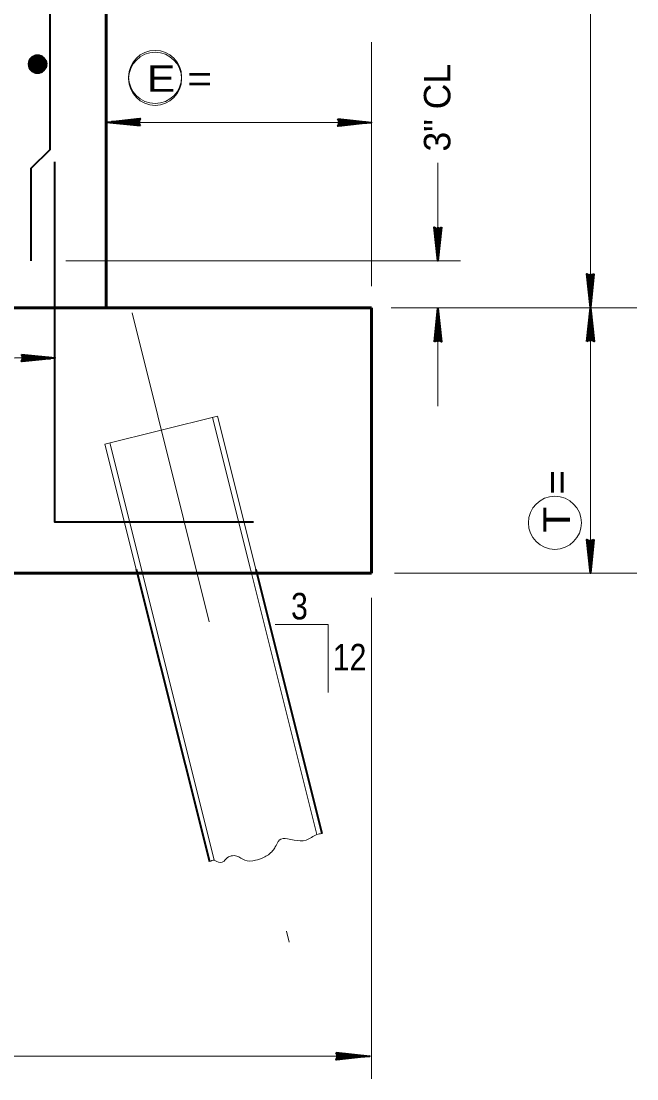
# Model space of a CAD drawing. Extents: x 3.64 to 6.84, y -0.8 to 1.19.
# Drawn here: x 5.2422 to 5.4356, y -0.3007 to 0.0313 of the extents above; entities that cross this region are included whole.
import ezdxf
from ezdxf.enums import TextEntityAlignment as Align

# ---------------------------------------------------------------- set-up
doc = ezdxf.new("R2010")
doc.units = 0
doc.header["$LTSCALE"] = 0.0033
doc.linetypes.add('DOT_DASHED', pattern=[7.7, 5, -1.2, 0.3, -1.2])
doc.linetypes.add('MEDIUM_DASHED', pattern=[4.5, 3, -1.5])
doc.layers.add('1', color=7, linetype='Continuous', lineweight=40)
doc.layers.add('5', color=7, linetype='MEDIUM_DASHED', lineweight=13)

msp = doc.modelspace()

# ---------------------------------------------------------------- linework, layer by layer
at = {"layer": '1', "lineweight": 13}
for p, q in [((5.421, -0.141167), (5.421, 0.274583)), ((5.35225, -0.051917), (5.35225, 0.024667)), ((5.2705, -0.0005), (5.35225, -0.0005)), ((5.373083, -0.034083), (5.373083, -0.01325)), ((5.256167, -0.044), (5.380167, -0.044)), ((5.358417, -0.058667), (5.435583, -0.058667)), ((5.373083, -0.089583), (5.373083, -0.06875)), ((5.304833, -0.142), (5.346833, -0.142)), ((5.359417, -0.142), (5.435583, -0.142)), ((5.35225, -0.149667), (5.35225, -0.300667)), ((5.321917, -0.158083), (5.338583, -0.158083)), ((5.338583, -0.158083), (5.338583, -0.179417)), ((5.018417, -0.2935), (5.35175, -0.2935))]:
    msp.add_line(p, q, dxfattribs=at)
at = {"layer": '1'}
for p, q in [((5.249667, 0.019), (5.248417, 0.020167)), ((5.245167, 0.017083), (5.249083, 0.016333)), ((5.245167, 0.016917), (5.249, 0.016167)), ((5.245167, 0.016667), (5.249, 0.016)), ((5.24525, 0.019333), (5.249833, 0.017167)), ((5.24525, 0.0175), (5.249167, 0.01675)), ((5.245333, 0.017917), (5.249167, 0.017167)), ((5.245333, 0.01775), (5.249167, 0.017)), ((5.245417, 0.018333), (5.24925, 0.017667)), ((5.245417, 0.018167), (5.24925, 0.017417)), ((5.2455, 0.018917), (5.249417, 0.018167)), ((5.2455, 0.01875), (5.249417, 0.018)), ((5.2455, 0.0185), (5.249333, 0.01775)), ((5.245583, 0.019333), (5.2495, 0.018667)), ((5.245583, 0.019167), (5.2495, 0.018417)), ((5.245667, 0.019667), (5.2495, 0.019)), ((5.247583, 0.018833), (5.248917, 0.019833)), ((5.245083, 0.016583), (5.248917, 0.015833)), ((5.245083, 0.016417), (5.248917, 0.015667)), ((5.249417, 0.016167), (5.245667, 0.01575))]:
    msp.add_line(p, q, dxfattribs=at)
at = {"layer": '1', "lineweight": 60}
for p, q in [((5.249833, 0.017167), (5.245083, 0.016417)), ((5.2455, 0.019333), (5.245333, 0.016417)), ((5.24575, 0.019333), (5.2455, 0.016417)), ((5.245917, 0.019333), (5.24575, 0.016333)), ((5.246083, 0.019333), (5.245833, 0.016333)), ((5.24625, 0.019333), (5.246083, 0.016333)), ((5.2465, 0.019333), (5.246333, 0.016333)), ((5.24675, 0.019333), (5.2465, 0.016333)), ((5.246833, 0.01925), (5.246667, 0.016333)), ((5.247, 0.01925), (5.246833, 0.016333)), ((5.247167, 0.01925), (5.247, 0.016333)), ((5.247417, 0.01925), (5.247167, 0.016333)), ((5.247583, 0.01925), (5.247417, 0.016333)), ((5.247833, 0.019167), (5.247583, 0.01625)), ((5.248083, 0.019167), (5.247833, 0.01625)), ((5.24825, 0.019167), (5.248083, 0.01625)), ((5.248333, 0.019167), (5.248167, 0.01625)), ((5.2485, 0.019167), (5.248333, 0.01625)), ((5.248583, 0.019167), (5.248417, 0.01625)), ((5.248833, 0.019083), (5.248583, 0.016167)), ((5.249, 0.019083), (5.248833, 0.016167)), ((5.249167, 0.019083), (5.248917, 0.016167)), ((5.249333, 0.019083), (5.249167, 0.016167)), ((5.249583, 0.019083), (5.249417, 0.016167)), ((5.249833, 0.017167), (5.249667, 0.019)), ((5.35225, -0.058667), (5.35225, -0.142)), ((5.35225, -0.142), (5.018917, -0.142))]:
    msp.add_line(p, q, dxfattribs=at)
at = {"layer": '1', "lineweight": 35}
for p, q in [((5.279333, 0.000583), (5.272, -0.00025)), ((5.279333, 0.000417), (5.272, -0.000333)), ((5.279333, 0.000333), (5.272, -0.0005)), ((5.279417, 0.000167), (5.272083, -0.000583)), ((5.341917, 0.0005), (5.34975, -0.000417)), ((5.341917, 0.0005), (5.34975, -0.000417)), ((5.341917, 0.000417), (5.34975, -0.000417)), ((5.341917, 0.000333), (5.34975, -0.0005)), ((5.341917, 0.000333), (5.34975, -0.000667)), ((5.279583, -0.0005), (5.269, -0.0005)), ((5.279333, -0.001333), (5.2715, -0.000333)), ((5.279333, -0.001333), (5.2715, -0.0005)), ((5.279333, -0.0015), (5.2715, -0.000583)), ((5.279333, -0.0015), (5.2715, -0.000583)), ((5.279333, -0.001417), (5.2715, -0.000583)), ((5.341667, -0.0005), (5.35225, -0.0005)), ((5.341833, -0.001167), (5.349167, -0.000417)), ((5.341917, -0.001333), (5.34925, -0.0005)), ((5.341917, -0.001417), (5.34925, -0.000667)), ((5.341917, -0.001583), (5.34925, -0.00075)), ((5.372, -0.033667), (5.372833, -0.041)), ((5.372167, -0.033667), (5.372917, -0.041)), ((5.37225, -0.033667), (5.373083, -0.041)), ((5.372417, -0.033583), (5.373167, -0.040917)), ((5.373917, -0.033667), (5.372917, -0.0415)), ((5.373083, -0.033417), (5.373083, -0.044)), ((5.373917, -0.033667), (5.373083, -0.0415)), ((5.374083, -0.033667), (5.373167, -0.0415)), ((5.374083, -0.033667), (5.373167, -0.0415)), ((5.374, -0.033667), (5.373167, -0.0415)), ((5.419917, -0.04825), (5.42075, -0.055583)), ((5.420083, -0.04825), (5.420833, -0.055583)), ((5.420167, -0.04825), (5.421, -0.055583)), ((5.420333, -0.048167), (5.421083, -0.0555)), ((5.421833, -0.04825), (5.420833, -0.056083)), ((5.421, -0.048), (5.421, -0.058583)), ((5.421833, -0.04825), (5.421, -0.056083)), ((5.422, -0.04825), (5.421083, -0.056083)), ((5.422, -0.04825), (5.421083, -0.056083)), ((5.421917, -0.04825), (5.421083, -0.056083)), ((5.373083, -0.069417), (5.373083, -0.058833)), ((5.421, -0.06925), (5.421, -0.058667)), ((5.372083, -0.069167), (5.373, -0.061333)), ((5.372083, -0.069167), (5.373, -0.061333)), ((5.372167, -0.069167), (5.373, -0.061333)), ((5.37225, -0.069167), (5.373083, -0.061333)), ((5.37225, -0.069167), (5.37325, -0.061333)), ((5.37375, -0.06925), (5.373, -0.061917)), ((5.373917, -0.069167), (5.373083, -0.061833)), ((5.374, -0.069167), (5.37325, -0.061833)), ((5.374167, -0.069167), (5.373333, -0.061833)), ((5.42, -0.069), (5.420917, -0.061167)), ((5.42, -0.069), (5.420917, -0.061167)), ((5.420083, -0.069), (5.420917, -0.061167)), ((5.420167, -0.069), (5.421, -0.061167)), ((5.420167, -0.069), (5.421167, -0.061167)), ((5.421667, -0.069083), (5.420917, -0.06175)), ((5.421833, -0.069), (5.421, -0.061667)), ((5.421917, -0.069), (5.421167, -0.061667)), ((5.422083, -0.069), (5.42125, -0.061667)), ((5.24225, -0.074417), (5.252833, -0.074417)), ((5.242417, -0.075083), (5.24975, -0.074333)), ((5.2425, -0.073417), (5.250333, -0.074333)), ((5.2425, -0.073417), (5.250333, -0.074333)), ((5.2425, -0.0735), (5.250333, -0.074333)), ((5.2425, -0.073583), (5.250333, -0.074417)), ((5.2425, -0.073583), (5.250333, -0.074583)), ((5.2425, -0.07525), (5.249833, -0.074417)), ((5.2425, -0.075333), (5.249833, -0.074583)), ((5.2425, -0.0755), (5.249833, -0.074667)), ((5.419917, -0.131667), (5.42075, -0.139)), ((5.420083, -0.131667), (5.420833, -0.139)), ((5.420167, -0.131667), (5.421, -0.139)), ((5.420333, -0.131583), (5.421083, -0.138917)), ((5.421833, -0.131667), (5.420833, -0.1395)), ((5.421, -0.131417), (5.421, -0.142)), ((5.421833, -0.131667), (5.421, -0.1395)), ((5.422, -0.131667), (5.421083, -0.1395)), ((5.422, -0.131667), (5.421083, -0.1395)), ((5.421917, -0.131667), (5.421083, -0.1395)), ((5.341083, -0.2935), (5.351667, -0.2935)), ((5.34125, -0.294167), (5.348583, -0.293417)), ((5.341333, -0.2925), (5.349167, -0.293417)), ((5.341333, -0.2925), (5.349167, -0.293417)), ((5.341333, -0.292583), (5.349167, -0.293417)), ((5.341333, -0.292667), (5.349167, -0.2935)), ((5.341333, -0.292667), (5.349167, -0.293667)), ((5.341333, -0.294333), (5.348667, -0.2935)), ((5.341333, -0.294417), (5.348667, -0.293667)), ((5.341333, -0.294583), (5.348667, -0.29375))]:
    msp.add_line(p, q, dxfattribs=at)
at = {"layer": '1', "lineweight": 60}
for points in [[(5.018917, -0.058667), (5.10225, -0.058667), (5.10225, 0.274667), (5.268917, 0.274667), (5.268917, -0.058667), (5.35225, -0.058667)], [(5.248917, 0.015667), (5.248917, 0.019833), (5.24725, 0.015167), (5.24775, 0.020333), (5.245667, 0.01575), (5.246417, 0.02025), (5.248, 0.01525), (5.244833, 0.018583), (5.249667, 0.019), (5.246417, 0.015333), (5.248417, 0.020167), (5.24525, 0.019333), (5.245083, 0.016417)], [(5.245667, 0.01575), (5.247167, 0.018), (5.245, 0.018917), (5.247, 0.020333), (5.247167, 0.018083), (5.248833, 0.01575), (5.244833, 0.018083), (5.247583, 0.018833)], [(5.248417, 0.020167), (5.247167, 0.018), (5.249417, 0.016167)], [(5.244667, 0.017667), (5.249833, 0.018333), (5.24525, 0.019333)], [(5.10225, -0.058667), (5.16475, -0.058667), (5.16475, -0.037833), (5.206417, -0.037833), (5.206417, -0.058667), (5.268917, -0.058667)]]:
    msp.add_lwpolyline(points, dxfattribs=at)
at = {"layer": '1'}
for points in [[(5.245333, -0.044), (5.245333, -0.014917), (5.25125, -0.009), (5.25125, 0.199333), (5.245333, 0.20525), (5.245333, 0.253833)], [(5.245083, 0.016417), (5.247167, 0.015167), (5.248917, 0.015667), (5.249833, 0.017167)], [(5.252667, -0.012917), (5.252667, -0.125917), (5.315167, -0.125917)]]:
    msp.add_lwpolyline(points, dxfattribs=at)
at = {"layer": '1', "lineweight": 35}
for points in [[(5.279583, -0.001583), (5.269, -0.0005), (5.279583, 0.000667), (5.279, -0.0005)], [(5.278833, -0.000583), (5.274167, -0.000667), (5.274167, -0.000583), (5.275083, -0.000583), (5.278833, -0.000667), (5.275833, -0.00075), (5.279, -0.000833), (5.27675, -0.000917), (5.279, -0.001), (5.2755, -0.00075), (5.270833, -0.000583), (5.27175, -0.000333), (5.2705, -0.000333), (5.278833, -0.000333), (5.276417, -0.000167), (5.279, -0.000167), (5.273667, -0.000583), (5.279, 0.000083)], [(5.341667, 0.000583), (5.35225, -0.0005), (5.341667, -0.001667), (5.34225, -0.0005)], [(5.342417, -0.000417), (5.347083, -0.000333), (5.347083, -0.000417), (5.346167, -0.000417), (5.342417, -0.000333), (5.345417, -0.00025), (5.34225, -0.000167), (5.3445, -0.000083), (5.34225, 0), (5.34575, -0.00025), (5.350417, -0.000417), (5.3495, -0.000667), (5.35075, -0.000667), (5.342417, -0.000667), (5.344833, -0.000833), (5.34225, -0.000833), (5.347583, -0.000417), (5.34225, -0.001083)], [(5.374167, -0.033417), (5.373083, -0.044), (5.371917, -0.033417), (5.373083, -0.034)], [(5.373167, -0.034167), (5.37325, -0.038833), (5.373167, -0.038833), (5.373167, -0.037917), (5.37325, -0.034167), (5.373333, -0.037167), (5.373417, -0.034), (5.3735, -0.03625), (5.373583, -0.034), (5.373333, -0.0375), (5.373167, -0.042167), (5.372917, -0.04125), (5.372917, -0.0425), (5.372917, -0.034167), (5.37275, -0.036583), (5.37275, -0.034), (5.373167, -0.039333), (5.3725, -0.034)], [(5.422083, -0.048), (5.421, -0.058583), (5.419833, -0.048), (5.421, -0.048583)], [(5.421083, -0.04875), (5.421167, -0.053417), (5.421083, -0.053417), (5.421083, -0.0525), (5.421167, -0.04875), (5.42125, -0.05175), (5.421333, -0.048583), (5.421417, -0.050833), (5.4215, -0.048583), (5.42125, -0.052083), (5.421083, -0.05675), (5.420833, -0.055833), (5.420833, -0.057083), (5.420833, -0.04875), (5.420667, -0.051167), (5.420667, -0.048583), (5.421083, -0.053917), (5.420417, -0.048583)], [(5.372, -0.069417), (5.373083, -0.058833), (5.37425, -0.069417), (5.373083, -0.068833)], [(5.419917, -0.06925), (5.421, -0.058667), (5.422167, -0.06925), (5.421, -0.068667)], [(5.373, -0.068667), (5.372917, -0.064), (5.373, -0.064), (5.373, -0.064917), (5.372917, -0.068667), (5.372833, -0.065667), (5.37275, -0.068833), (5.372667, -0.066583), (5.372583, -0.068833), (5.372833, -0.065333), (5.373, -0.060667), (5.37325, -0.061583), (5.37325, -0.060333), (5.37325, -0.068667), (5.373417, -0.06625), (5.373417, -0.068833), (5.373, -0.0635), (5.373667, -0.068833)], [(5.420917, -0.0685), (5.420833, -0.063833), (5.420917, -0.063833), (5.420917, -0.06475), (5.420833, -0.0685), (5.42075, -0.0655), (5.420667, -0.068667), (5.420583, -0.066417), (5.4205, -0.068667), (5.42075, -0.065167), (5.420917, -0.0605), (5.421167, -0.061417), (5.421167, -0.060167), (5.421167, -0.0685), (5.421333, -0.066083), (5.421333, -0.068667), (5.420917, -0.063333), (5.421583, -0.068667)], [(5.24225, -0.073333), (5.252833, -0.074417), (5.24225, -0.075583), (5.242833, -0.074417)], [(5.243, -0.074333), (5.247667, -0.07425), (5.247667, -0.074333), (5.24675, -0.074333), (5.243, -0.07425), (5.246, -0.074167), (5.242833, -0.074083), (5.245083, -0.074), (5.242833, -0.073917), (5.246333, -0.074167), (5.251, -0.074333), (5.250083, -0.074583), (5.251333, -0.074583), (5.243, -0.074583), (5.245417, -0.07475), (5.242833, -0.07475), (5.248167, -0.074333), (5.242833, -0.075)], [(5.422083, -0.131417), (5.421, -0.142), (5.419833, -0.131417), (5.421, -0.132)], [(5.421083, -0.132167), (5.421167, -0.136833), (5.421083, -0.136833), (5.421083, -0.135917), (5.421167, -0.132167), (5.42125, -0.135167), (5.421333, -0.132), (5.421417, -0.13425), (5.4215, -0.132), (5.42125, -0.1355), (5.421083, -0.140167), (5.420833, -0.13925), (5.420833, -0.1405), (5.420833, -0.132167), (5.420667, -0.134583), (5.420667, -0.132), (5.421083, -0.137333), (5.420417, -0.132)], [(5.341083, -0.292417), (5.351667, -0.2935), (5.341083, -0.294667), (5.341667, -0.2935)], [(5.341833, -0.293417), (5.3465, -0.293333), (5.3465, -0.293417), (5.345583, -0.293417), (5.341833, -0.293333), (5.344833, -0.29325), (5.341667, -0.293167), (5.343917, -0.293083), (5.341667, -0.293), (5.345167, -0.29325), (5.349833, -0.293417), (5.348917, -0.293667), (5.350167, -0.293667), (5.341833, -0.293667), (5.34425, -0.293833), (5.341667, -0.293833), (5.347, -0.293417), (5.341667, -0.294083)]]:
    msp.add_lwpolyline(points, close=True, dxfattribs=at)
for points in [[(5.278833, -0.000583), (5.27925, -0.001333), (5.279, -0.001083), (5.278833, -0.00075), (5.278583, -0.000833), (5.27875, -0.001167), (5.278917, -0.000417), (5.279083, 0.000083), (5.279333, 0.0005)], [(5.342417, -0.000417), (5.342, 0.000333), (5.34225, 0.000083), (5.342417, -0.00025), (5.342667, -0.000167), (5.3425, 0.000167), (5.342333, -0.000583), (5.342167, -0.001083), (5.341917, -0.0015)], [(5.373167, -0.034167), (5.373917, -0.03375), (5.373667, -0.034), (5.373333, -0.034167), (5.373417, -0.034417), (5.37375, -0.03425), (5.373, -0.034083), (5.3725, -0.033917), (5.372083, -0.033667)], [(5.421083, -0.04875), (5.421833, -0.048333), (5.421583, -0.048583), (5.42125, -0.04875), (5.421333, -0.049), (5.421667, -0.048833), (5.420917, -0.048667), (5.420417, -0.0485), (5.42, -0.04825)], [(5.373, -0.068667), (5.37225, -0.069083), (5.3725, -0.068833), (5.372833, -0.068667), (5.37275, -0.068417), (5.372417, -0.068583), (5.373167, -0.06875), (5.373667, -0.068917), (5.374083, -0.069167)], [(5.420917, -0.0685), (5.420167, -0.068917), (5.420417, -0.068667), (5.42075, -0.0685), (5.420667, -0.06825), (5.420333, -0.068417), (5.421083, -0.068583), (5.421583, -0.06875), (5.422, -0.069)], [(5.243, -0.074333), (5.242583, -0.073583), (5.242833, -0.073833), (5.243, -0.074167), (5.24325, -0.074083), (5.243083, -0.07375), (5.242917, -0.0745), (5.24275, -0.075), (5.2425, -0.075417)], [(5.421083, -0.132167), (5.421833, -0.13175), (5.421583, -0.132), (5.42125, -0.132167), (5.421333, -0.132417), (5.421667, -0.13225), (5.420917, -0.132083), (5.420417, -0.131917), (5.42, -0.131667)], [(5.341833, -0.293417), (5.341417, -0.292667), (5.341667, -0.292917), (5.341833, -0.29325), (5.342083, -0.293167), (5.341917, -0.292833), (5.34175, -0.293583), (5.341583, -0.294083), (5.341333, -0.2945)]]:
    msp.add_lwpolyline(points, dxfattribs=at)
at = {"layer": '1', "lineweight": 60}
msp.add_circle((5.247333, 0.017767), 0.00264, dxfattribs=at)
at = {"layer": '1', "lineweight": 13}
for centre in [(5.28425, 0.01375), (5.28425, 0.013167), (5.409833, -0.126167)]:
    msp.add_circle(centre, 0.008333, dxfattribs=at)
msp.add_arc((5.240845, -0.150605), 0.076202, 88.94317, 139.38493, dxfattribs=at)
at = {"layer": '5', "linetype": 'DOT_DASHED'}
msp.add_line((5.277, -0.06025), (5.326333, -0.25775), dxfattribs=at)
at = {"layer": '5'}
for p, q in [((5.303833, -0.092667), (5.2685, -0.1015)), ((5.303833, -0.092667), (5.315833, -0.14075)), ((5.30225, -0.093083), (5.31425, -0.14075)), ((5.2685, -0.1015), (5.278333, -0.14075)), ((5.27, -0.101083), (5.279917, -0.14075))]:
    msp.add_line(p, q, dxfattribs=at)
at = {"layer": '5', "linetype": 'Continuous', "lineweight": 35}
for p, q in [((5.278333, -0.14075), (5.301333, -0.2325)), ((5.315833, -0.14075), (5.336583, -0.223667))]:
    msp.add_line(p, q, dxfattribs=at)
at = {"layer": '5', "linetype": 'Continuous'}
for p, q in [((5.279917, -0.14075), (5.302833, -0.232083)), ((5.31425, -0.14075), (5.335083, -0.224))]:
    msp.add_line(p, q, dxfattribs=at)
msp.add_spline([(5.336583, -0.223667), (5.335083, -0.224), (5.331667, -0.22575), (5.327917, -0.22575), (5.325833, -0.225333), (5.32325, -0.22575), (5.322917, -0.226167), (5.322, -0.227833), (5.321167, -0.229083), (5.31825, -0.23125), (5.31575, -0.232083), (5.312417, -0.232083), (5.309917, -0.23075), (5.306583, -0.231583), (5.30575, -0.2325), (5.303667, -0.2325), (5.302833, -0.232083), (5.301333, -0.2325)], degree=3, dxfattribs=at)

# ---------------------------------------------------------------- texts
at = {"layer": '1'}
for s, width, p in [('E =      ', 1.2, (5.281667, 0.009083)), ('12', 0.85, (5.340083, -0.1725))]:
    msp.add_text(s, height=0.008334, dxfattribs=dict(at, width=width)).set_placement(p)
msp.add_text('3" CL', height=0.008334, rotation=90, dxfattribs=at).set_placement((5.377, -0.009667))
at = {"layer": '1', "width": 1.2}
msp.add_text('T =      ', height=0.008334, rotation=90, dxfattribs=at).set_placement((5.414583, -0.12925))
at = {"layer": '1', "width": 0.85}
msp.add_text('3', height=0.008334, dxfattribs=at).set_placement((5.329583, -0.1565), align=Align.CENTER)

doc.saveas('drawing.dxf')
